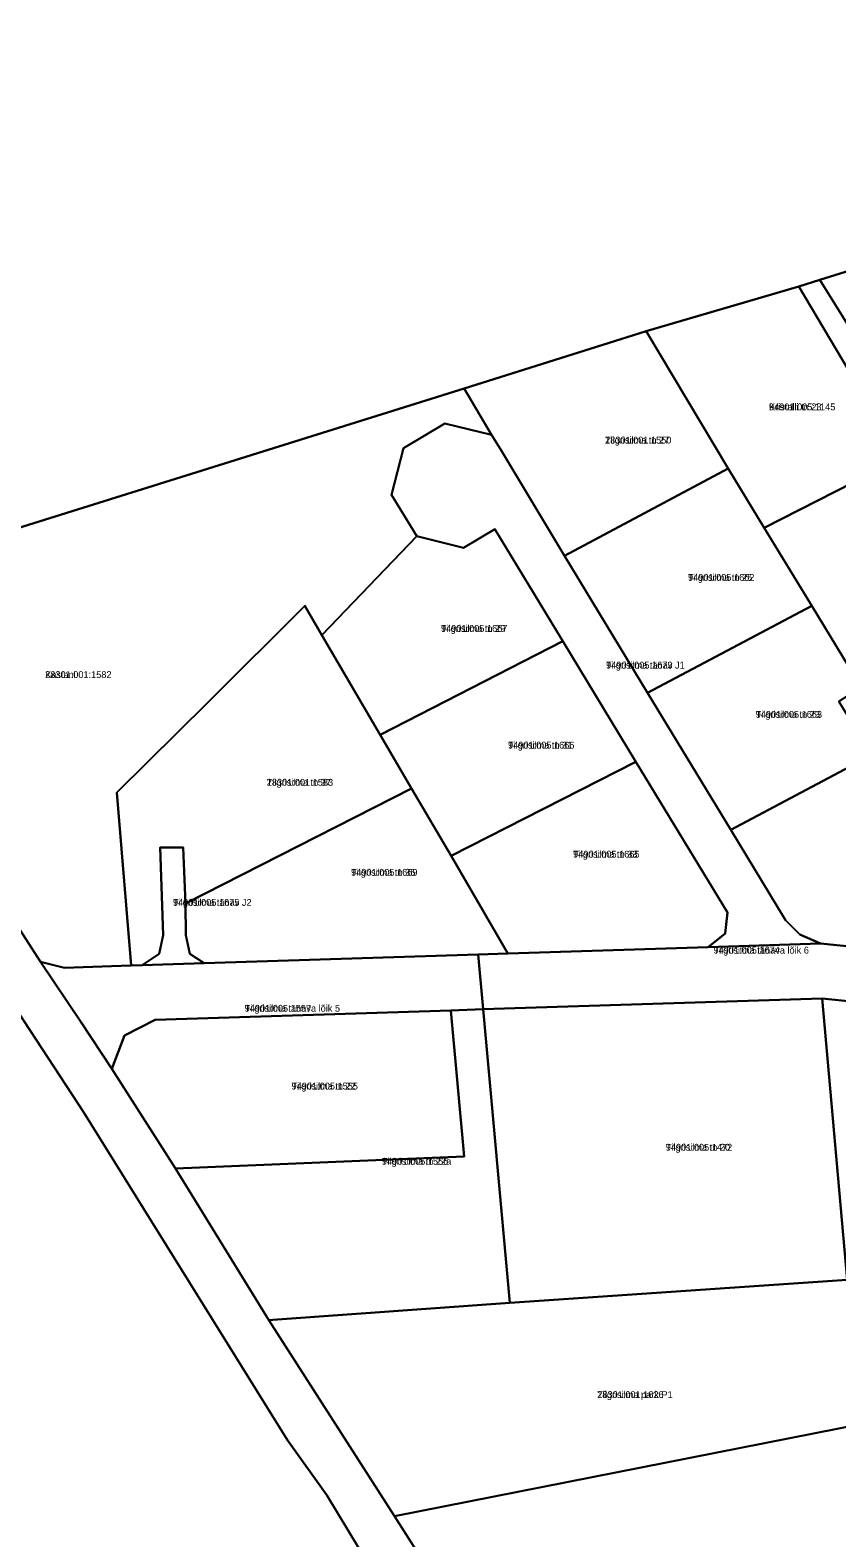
# Model space of a CAD drawing. Extents: x 647845 to 668483, y 6445298 to 6473683.
# Drawn here: x 655416.4 to 655592.6, y 6470382.6 to 6470712.1 of the extents above; entities that cross this region are included whole.
import ezdxf

# ---------------------------------------------------------------- set-up
doc = ezdxf.new("R2010")
doc.units = 0
for name, color, linetype in [('L_AADRESS', 7, 'Continuous'), ('PIIR', 7, 'Continuous'), ('TUNNUS', 7, 'Continuous')]:
    doc.layers.add(name, color=color, linetype=linetype)

msp = doc.modelspace()

# ---------------------------------------------------------------- linework, layer by layer
at = {"layer": 'PIIR'}
for points in [[(655412.92, 6470787.93), (655483.23, 6470815.62), (655692.58, 6470887.36), (655738.25, 6470830.73), (655784.98, 6470772.88), (655754, 6470753.36), (655720.68, 6470732.19), (655685.73, 6470710.01), (655652.81, 6470689.1), (655619.91, 6470668.18), (655616.71, 6470666.16), (655588.94, 6470657.53), (655584.3, 6470656.08), (655550.96, 6470646.26), (655545.46, 6470644.51), (655511.18, 6470633.78), (655367.08, 6470588.66)], [(655367.08, 6470588.66), (655418.61, 6470508.49), (655427.43, 6470495.33), (655434.2, 6470485.11), (655448.15, 6470463.31), (655468.5, 6470430.14), (655495.95, 6470387.34), (655520.92, 6470348.21), (655535.64, 6470324.89), (655559.35, 6470287.3), (655570.83, 6470269.6), (655580.69, 6470255.88), (655589.26, 6470245.76), (655598.27, 6470236.58), (655609.69, 6470226.39), (655621.32, 6470215.84), (655678.6, 6470164.4), (655754.45, 6470096.34), (655755.63, 6470095.26), (655758.8, 6470094.76), (655776.06, 6470091.89), (655753.07, 6470076.17)], [(655376.03, 6470555.01), (655428.13, 6470475.56), (655472.63, 6470403.91), (655481.21, 6470391.91), (655490.55, 6470376.51)], [(655753.45, 6470082.01), (655715.14, 6470118.31), (655625.44, 6470198.14), (655580.78, 6470239.74), (655572.75, 6470249.36), (655560.16, 6470266.8), (655548.8, 6470284.29), (655531.22, 6470312.11), (655507.4, 6470349.72), (655490.55, 6470376.51), (655481.21, 6470391.91), (655472.63, 6470403.91), (655428.13, 6470475.56), (655376.03, 6470555.01)]]:
    msp.add_lwpolyline(points, dxfattribs=at)
for points in [[(655634.51, 6470644.3), (655607.69, 6470627.26), (655588.94, 6470657.53), (655616.71, 6470666.16), (655619.91, 6470668.18)], [(655607.69, 6470627.26), (655606.29, 6470625.64), (655604.63, 6470621.83), (655584.3, 6470656.08), (655588.94, 6470657.53)], [(655550.96, 6470646.26), (655584.3, 6470656.08), (655604.63, 6470621.83), (655604.1, 6470617.24), (655576.73, 6470603.28), (655568.88, 6470616.24)], [(655517.14, 6470623.62), (655511.18, 6470633.78), (655545.46, 6470644.51), (655550.96, 6470646.26), (655568.88, 6470616.24), (655533.09, 6470597.2), (655519.14, 6470620.49)], [(655418.61, 6470508.49), (655367.08, 6470588.66), (655511.18, 6470633.78), (655517.14, 6470623.62), (655506.95, 6470626.13), (655497.94, 6470620.72), (655495.35, 6470610.53), (655500.85, 6470601.49), (655480.1, 6470579.89), (655476.42, 6470586.24), (655455.25, 6470565.23), (655435.3, 6470545.44), (655438.42, 6470507.66), (655434.14, 6470507.52), (655423.88, 6470507.18)], [(655589.08, 6470512.46), (655564.52, 6470511.7), (655568.2, 6470514.68), (655568.71, 6470519.28), (655548.73, 6470552.2), (655532.75, 6470578.54), (655517.87, 6470603.05), (655511.04, 6470598.94), (655500.85, 6470601.49), (655495.35, 6470610.53), (655497.94, 6470620.72), (655506.95, 6470626.13), (655517.14, 6470623.62), (655519.14, 6470620.49), (655533.09, 6470597.2), (655551.27, 6470567.22), (655569.44, 6470537.3), (655581.38, 6470517.61), (655584.57, 6470514.46)], [(655576.73, 6470603.28), (655604.1, 6470617.24), (655604.69, 6470615.01), (655623.47, 6470584.33), (655597.98, 6470568.46), (655587.17, 6470586.3)], [(655551.27, 6470567.22), (655533.09, 6470597.2), (655568.88, 6470616.24), (655576.73, 6470603.28), (655587.17, 6470586.3)], [(655500.85, 6470601.49), (655511.04, 6470598.94), (655517.87, 6470603.05), (655532.75, 6470578.54), (655492.83, 6470558.11), (655480.1, 6470579.89)], [(655440.82, 6470507.77), (655438.42, 6470507.66), (655435.3, 6470545.44), (655455.25, 6470565.23), (655476.42, 6470586.24), (655480.1, 6470579.89), (655492.83, 6470558.11), (655499.66, 6470546.36), (655450.28, 6470521.25), (655449.8, 6470533.44), (655444.81, 6470533.43), (655445.41, 6470514.28), (655444.56, 6470510.19)], [(655569.44, 6470537.3), (655551.27, 6470567.22), (655587.17, 6470586.3), (655597.98, 6470568.46), (655593.05, 6470565.38), (655600.23, 6470553.6)], [(655532.75, 6470578.54), (655548.73, 6470552.2), (655508.35, 6470531.61), (655499.66, 6470546.36), (655492.83, 6470558.11)], [(655548.73, 6470552.2), (655568.71, 6470519.28), (655568.2, 6470514.68), (655564.52, 6470511.7), (655520.76, 6470510.28), (655508.35, 6470531.61)], [(655627.69, 6470508.58), (655589.08, 6470512.46), (655584.57, 6470514.46), (655581.38, 6470517.61), (655569.44, 6470537.3), (655600.23, 6470553.6), (655612.9, 6470532.83)], [(655520.76, 6470510.28), (655514.25, 6470510.04), (655454.36, 6470508.2), (655451.29, 6470510.19), (655450.42, 6470514.27), (655450.28, 6470521.25), (655499.66, 6470546.36), (655508.35, 6470531.61)], [(655454.36, 6470508.2), (655440.82, 6470507.77), (655444.56, 6470510.19), (655445.41, 6470514.28), (655444.81, 6470533.43), (655449.8, 6470533.44), (655450.28, 6470521.25), (655450.42, 6470514.27), (655451.29, 6470510.19)], [(655634.56, 6470495.82), (655589.43, 6470500.46), (655515.32, 6470498.12), (655514.25, 6470510.04), (655520.76, 6470510.28), (655564.52, 6470511.7), (655589.08, 6470512.46), (655627.69, 6470508.58), (655634.89, 6470507.85), (655638.42, 6470502.18), (655713.46, 6470505.07), (655741.87, 6470524.72), (655742.81, 6470522.9), (655743.45, 6470521.73), (655744.38, 6470520.2), (655739.56, 6470516.54), (655738.96, 6470516.11), (655713.68, 6470502.61), (655706.34, 6470501.12), (655694.52, 6470499.83), (655685.55, 6470498.81), (655670.68, 6470497.51), (655665.74, 6470497.14)], [(655434.2, 6470485.11), (655427.43, 6470495.33), (655418.61, 6470508.49), (655423.88, 6470507.18), (655434.14, 6470507.52), (655438.42, 6470507.66), (655440.82, 6470507.77), (655454.36, 6470508.2), (655514.25, 6470510.04), (655515.32, 6470498.12), (655508.28, 6470497.82), (655443.72, 6470495.77), (655437.01, 6470492.35)], [(655515.32, 6470498.12), (655589.43, 6470500.46), (655594.88, 6470438.95), (655521.19, 6470433.93)], [(655589.43, 6470500.46), (655629.76, 6470496.32), (655635.42, 6470444.49), (655628.58, 6470443.32), (655606.39, 6470439.56), (655594.88, 6470438.95)], [(655434.2, 6470485.11), (655437.01, 6470492.35), (655443.72, 6470495.77), (655508.28, 6470497.82), (655511.22, 6470465.91), (655448.15, 6470463.31)], [(655508.28, 6470497.82), (655515.32, 6470498.12), (655521.19, 6470433.93), (655469.4, 6470430.23), (655468.5, 6470430.14), (655448.15, 6470463.31), (655511.22, 6470465.91)], [(655603.77, 6470408.63), (655495.95, 6470387.34), (655468.5, 6470430.14), (655469.4, 6470430.23), (655521.19, 6470433.93), (655594.88, 6470438.95), (655595.74, 6470429.95), (655605.2, 6470429.74), (655598.36, 6470417.91)], [(655520.92, 6470348.21), (655495.95, 6470387.34), (655603.77, 6470408.63), (655605.35, 6470405.77), (655612.19, 6470405.76), (655626.92, 6470377.86), (655535.64, 6470324.89)]]:
    msp.add_lwpolyline(points, close=True, dxfattribs=at)

# ---------------------------------------------------------------- texts
at = {"layer": 'L_AADRESS'}
for s, p in [('Kristalli tn 23', (655577.8, 6470628.99)), ('Tiigrisilma tn 27', (655541.98, 6470621.73)), ('Tiigrisilma tn 25', (655560.12, 6470591.73)), ('Tiigrisilma tn 29', (655506.14, 6470580.58)), ('Tiigrisilma tänav J1', (655542.21, 6470572.55)), ('Kastani', (655419.65, 6470570.48)), ('Tiigrisilma tn 23', (655574.9, 6470561.8)), ('Tiigrisilma tn 31', (655520.79, 6470555.07)), ('Tiigrisilma tn 37', (655468.07, 6470546.95)), ('Tiigrisilma tn 33', (655535.01, 6470531.24)), ('Tiigrisilma tn 35', (655486.5, 6470527.28)), ('Tiigrisilma tänav J2', (655447.59, 6470520.71)), ('Tiigrisilma tänava lõik 6', (655565.68, 6470510.27)), ('Tiigrisilma tänava lõik 5', (655463.24, 6470497.57)), ('Tiigrisilma tn 22', (655473.49, 6470480.57)), ('Tiigrisilma tn 20', (655555.26, 6470467.2)), ('Tiigrisilma tn 22a', (655493.23, 6470464.13)), ('Tiigrisilma park P1', (655540.27, 6470413.15))]:
    msp.add_text(s, height=1.5, dxfattribs=at).set_placement(p)
at = {"layer": 'TUNNUS'}
for s, p in [('94901:005:1145', (655577.8, 6470628.99)), ('28301:001:1550', (655541.98, 6470621.73)), ('94901:005:1662', (655560.12, 6470591.73)), ('94901:005:1667', (655506.14, 6470580.58)), ('94901:005:1673', (655542.21, 6470572.55)), ('28301:001:1582', (655419.65, 6470570.48)), ('94901:005:1663', (655574.9, 6470561.8)), ('94901:005:1666', (655520.79, 6470555.07)), ('28301:001:1583', (655468.07, 6470546.95)), ('94901:005:1665', (655535.01, 6470531.24)), ('94901:005:1669', (655486.5, 6470527.28)), ('94901:005:1675', (655447.59, 6470520.71)), ('94901:005:1674', (655565.68, 6470510.27)), ('94901:005:1557', (655463.24, 6470497.57)), ('94901:005:1555', (655473.49, 6470480.57)), ('94901:005:1472', (655555.26, 6470467.2)), ('94901:005:1556', (655493.23, 6470464.13)), ('28301:001:1626', (655540.27, 6470413.15))]:
    msp.add_text(s, height=1.5, dxfattribs=at).set_placement(p)

doc.saveas('drawing.dxf')
